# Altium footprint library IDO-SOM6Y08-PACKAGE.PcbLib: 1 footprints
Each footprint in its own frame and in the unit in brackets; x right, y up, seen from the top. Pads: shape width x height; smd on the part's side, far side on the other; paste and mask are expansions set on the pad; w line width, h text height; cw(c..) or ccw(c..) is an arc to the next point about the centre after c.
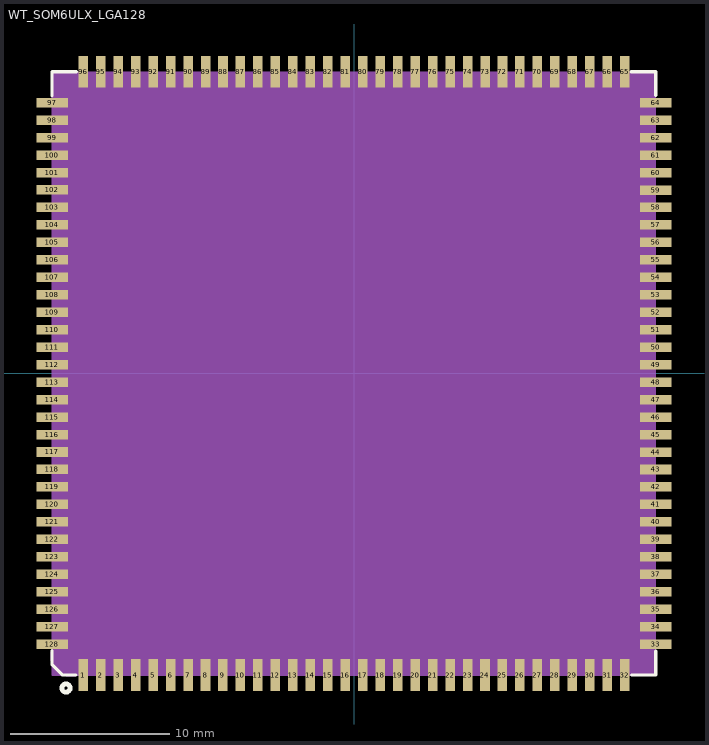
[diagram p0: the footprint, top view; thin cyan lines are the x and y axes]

## WT_SOM6ULX_LGA128 [mm] "WT_SOM6ULX_LGA128"
pads (128):
  rect 0.6x2 smd: 1(-17.051,-19) 2(-15.951,-19) 3(-14.851,-19) 4(-13.751,-19) 5(-12.651,-19) 6(-11.551,-19) 7(-10.451,-19) 8(-9.351,-19) 9(-8.251,-19) 10(-7.151,-19) 11(-6.051,-19) 12(-4.951,-19) 13(-3.851,-19) 14(-2.751,-19) 15(-1.651,-19) 16(-0.551,-19) 17(0.549,-19) 18(1.649,-19) 19(2.749,-19) 20(3.849,-19) 21(4.949,-19) 22(6.049,-19) 23(7.149,-19) 24(8.249,-19) 25(9.349,-19) 26(10.449,-19) 27(11.549,-19) 28(12.649,-19) 29(13.749,-19) 30(14.849,-19) 31(15.949,-19) 32(17.049,-19) 65(17.051,19) 66(15.951,19) 67(14.851,19) 68(13.751,19) 69(12.651,19) 70(11.551,19) 71(10.451,19) 72(9.351,19) 73(8.251,19) 74(7.151,19) 75(6.051,19) 76(4.951,19) 77(3.851,19) 78(2.751,19) 79(1.651,19) 80(0.551,19) 81(-0.549,19) 82(-1.649,19) 83(-2.749,19) 84(-3.849,19) 85(-4.949,19) 86(-6.049,19) 87(-7.149,19) 88(-8.249,19) 89(-9.349,19) 90(-10.449,19) 91(-11.549,19) 92(-12.649,19) 93(-13.749,19) 94(-14.849,19) 95(-15.949,19) 96(-17.049,19)
  rect 2x0.6 smd: 33(19,-17.051) 34(19,-15.951) 35(19,-14.851) 36(19,-13.751) 37(19,-12.651) 38(19,-11.551) 39(19,-10.451) 40(19,-9.351) 41(19,-8.251) 42(19,-7.151) 43(19,-6.051) 44(19,-4.951) 45(19,-3.851) 46(19,-2.751) 47(19,-1.651) 48(19,-0.551) 49(19,0.549) 50(19,1.649) 51(19,2.749) 52(19,3.849) 53(19,4.949) 54(19,6.049) 55(19,7.149) 56(19,8.249) 57(19,9.349) 58(19,10.449) 59(19,11.549) 60(19,12.649) 61(19,13.749) 62(19,14.849) 63(19,15.949) 64(19,17.049) 97(-19,17.051) 98(-19,15.951) 99(-19,14.851) 100(-19,13.751) 101(-19,12.651) 102(-19,11.551) 103(-19,10.451) 104(-19,9.351) 105(-19,8.251) 106(-19,7.151) 107(-19,6.051) 108(-19,4.951) 109(-19,3.851) 110(-19,2.751) 111(-19,1.651) 112(-19,0.551) 113(-19,-0.549) 114(-19,-1.649) 115(-19,-2.749) 116(-19,-3.849) 117(-19,-4.949) 118(-19,-6.049) 119(-19,-7.149) 120(-19,-8.249) 121(-19,-9.349) 122(-19,-10.449) 123(-19,-11.549) 124(-19,-12.649) 125(-19,-13.749) 126(-19,-14.849) 127(-19,-15.949) 128(-19,-17.049)
Top Overlay:
  circle w0.3: c-18.136,-19.813 r0.262
  lines w0.2: -19.025,-17.451 -19.025,-18.314 -18.34,-19 -17.527,-19 ; -19.025,17.474 -19.025,18.998 -17.476,18.998 ; 17.449,18.998 18.998,18.998 18.998,17.5 ; 17.474,-19 18.998,-19 18.998,-17.501
  text ".Designator" at -21.667,-17.476 h0.66
Mechanical 6:
  text "30" at 14.341,-19 h0.64
  text "59" at 18.492,11.549 h0.64
  text "60" at 18.492,12.649 h0.64
  text "65" at 16.543,19 h0.64
  text "62" at 18.492,14.849 h0.64
  text "91" at -12.057,19 h0.64
  text "21" at 4.441,-19 h0.64
  text "27" at 11.041,-19 h0.64
  text "39" at 18.492,-10.451 h0.64
  text "66" at 15.443,19 h0.64
  text "14" at -3.259,-19 h0.64
  text "22" at 5.541,-19 h0.64
  text "20" at 3.341,-19 h0.64
  text "97" at -19.508,17.051 h0.64
  text "64" at 18.492,17.049 h0.64
  text "8" at -9.605,-19 h0.64
  text "101" at -19.762,12.651 h0.64
  text "4" at -14.005,-19 h0.64
  text "23" at 6.641,-19 h0.64
  text "31" at 15.441,-19 h0.64
  text "11" at -6.559,-19 h0.64
  text "2" at -16.205,-19 h0.64
  text "102" at -19.762,11.551 h0.64
  text "12" at -5.459,-19 h0.64
  text "96" at -17.557,19 h0.64
  text "9" at -8.505,-19 h0.64
  text "26" at 9.941,-19 h0.64
  text "128" at -19.762,-17.049 h0.64
  text "16" at -1.059,-19 h0.64
  text "107" at -19.762,6.051 h0.64
  text "15" at -2.159,-19 h0.64
  text "29" at 13.241,-19 h0.64
  text "13" at -4.359,-19 h0.64
  text "19" at 2.241,-19 h0.64
  text "99" at -19.508,14.851 h0.64
  text "18" at 1.141,-19 h0.64
  text "24" at 7.741,-19 h0.64
  text "90" at -10.957,19 h0.64
  text "1" at -17.305,-19 h0.64
  text "95" at -16.457,19 h0.64
  text "25" at 8.841,-19 h0.64
  text "57" at 18.492,9.349 h0.64
  text "88" at -8.757,19 h0.64
  text "17" at 0.041,-19 h0.64
  text "103" at -19.762,10.451 h0.64
  text "58" at 18.492,10.449 h0.64
  text "6" at -11.805,-19 h0.64
  text "127" at -19.762,-15.949 h0.64
  text "61" at 18.492,13.749 h0.64
  text "92" at -13.157,19 h0.64
  text "94" at -15.357,19 h0.64
  text "46" at 18.492,-2.751 h0.64
  text "43" at 18.492,-6.051 h0.64
  text "100" at -19.762,13.751 h0.64
  text "45" at 18.492,-3.851 h0.64
  text "117" at -19.762,-4.949 h0.64
  text "67" at 14.343,19 h0.64
  text "122" at -19.762,-10.449 h0.64
  text "118" at -19.762,-6.049 h0.64
  text "120" at -19.762,-8.249 h0.64
  text "69" at 12.143,19 h0.64
  text "121" at -19.762,-9.349 h0.64
  text "124" at -19.762,-12.649 h0.64
  text "70" at 11.043,19 h0.64
  text "125" at -19.762,-13.749 h0.64
  text "123" at -19.762,-11.549 h0.64
  text "71" at 9.943,19 h0.64
  text "119" at -19.762,-7.149 h0.64
  text "72" at 8.843,19 h0.64
  text "74" at 6.643,19 h0.64
  text "75" at 5.543,19 h0.64
  text "76" at 4.443,19 h0.64
  text "77" at 3.343,19 h0.64
  text "79" at 1.143,19 h0.64
  text "80" at 0.043,19 h0.64
  text "82" at -2.157,19 h0.64
  text "83" at -3.257,19 h0.64
  text "84" at -4.357,19 h0.64
  text "85" at -5.457,19 h0.64
  text "87" at -7.657,19 h0.64
  text "116" at -19.762,-3.849 h0.64
  text "108" at -19.762,4.951 h0.64
  text "56" at 18.492,8.249 h0.64
  text "89" at -9.857,19 h0.64
  text "113" at -19.762,-0.549 h0.64
  text "34" at 18.492,-15.951 h0.64
  text "114" at -19.762,-1.649 h0.64
  text "33" at 18.492,-17.051 h0.64
  text "38" at 18.492,-11.551 h0.64
  text "63" at 18.492,15.949 h0.64
  text "111" at -19.762,1.651 h0.64
  text "112" at -19.762,0.551 h0.64
  text "68" at 13.243,19 h0.64
  text "109" at -19.762,3.851 h0.64
  text "110" at -19.762,2.751 h0.64
  text "54" at 18.492,6.049 h0.64
  text "105" at -19.762,8.251 h0.64
  text "51" at 18.492,2.749 h0.64
  text "52" at 18.492,3.849 h0.64
  text "106" at -19.762,7.151 h0.64
  text "40" at 18.492,-9.351 h0.64
  text "53" at 18.492,4.949 h0.64
  text "86" at -6.557,19 h0.64
  text "50" at 18.492,1.649 h0.64
  text "49" at 18.492,0.549 h0.64
  text "41" at 18.492,-8.251 h0.64
  text "48" at 18.492,-0.551 h0.64
  text "44" at 18.492,-4.951 h0.64
  text "93" at -14.257,19 h0.64
  text "47" at 18.492,-1.651 h0.64
  text "10" at -7.659,-19 h0.64
  text "32" at 16.541,-19 h0.64
  text "3" at -15.105,-19 h0.64
  text "104" at -19.762,9.351 h0.64
  text "7" at -10.705,-19 h0.64
  text "28" at 12.141,-19 h0.64
  text "36" at 18.492,-13.751 h0.64
  text "37" at 18.492,-12.651 h0.64
  text "35" at 18.492,-14.851 h0.64
  text "115" at -19.762,-2.749 h0.64
  text "126" at -19.762,-14.849 h0.64
  text "5" at -12.905,-19 h0.64
  text "78" at 2.243,19 h0.64
  text "81" at -1.057,19 h0.64
  text "98" at -19.508,15.951 h0.64
  text "55" at 18.492,7.149 h0.64
  text "42" at 18.492,-7.151 h0.64
  text "73" at 7.743,19 h0.64
Mechanical 7:
  region: -19,-19 19,-19 19,19 -19,19
Mechanical 8:
  lines w0.025: -19,-19 19,-19 19,19 -19,19 -19,-19
  lines w0.2: -19,-17.552 -19,-18.06 -18.06,-19 -17.552,-19
3D body: height 3.81, standoff 0, extent -19,-19 19,19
